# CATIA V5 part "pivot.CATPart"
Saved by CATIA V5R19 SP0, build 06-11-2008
Part number: pivot
Publications: "e", "r"
Bounding box of the stored display mesh (mm): x 0 to 20, y -5 to 5, z -5 to 5
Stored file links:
  G:\EU_thinkMotion\CFAO_2010\MMS_groupe3\MMS_groupe3\A reprendre\evulliez\evulliez\pivot.CATPart
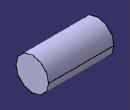
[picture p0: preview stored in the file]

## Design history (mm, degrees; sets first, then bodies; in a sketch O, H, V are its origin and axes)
Parameters
  e = 20 mm
  r = 5 mm
Body1 (main body)
  Sketch1 on yz-plane, origin (0, 0, 0), H (0, 1, 0), V (0, 0, 1)
    circle A1 centre (0, 0) radius 5
    radius A1 = 5 {= r}
  Pad1: profile Sketch1, direction (1, 0, 0), length 20 {= e}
